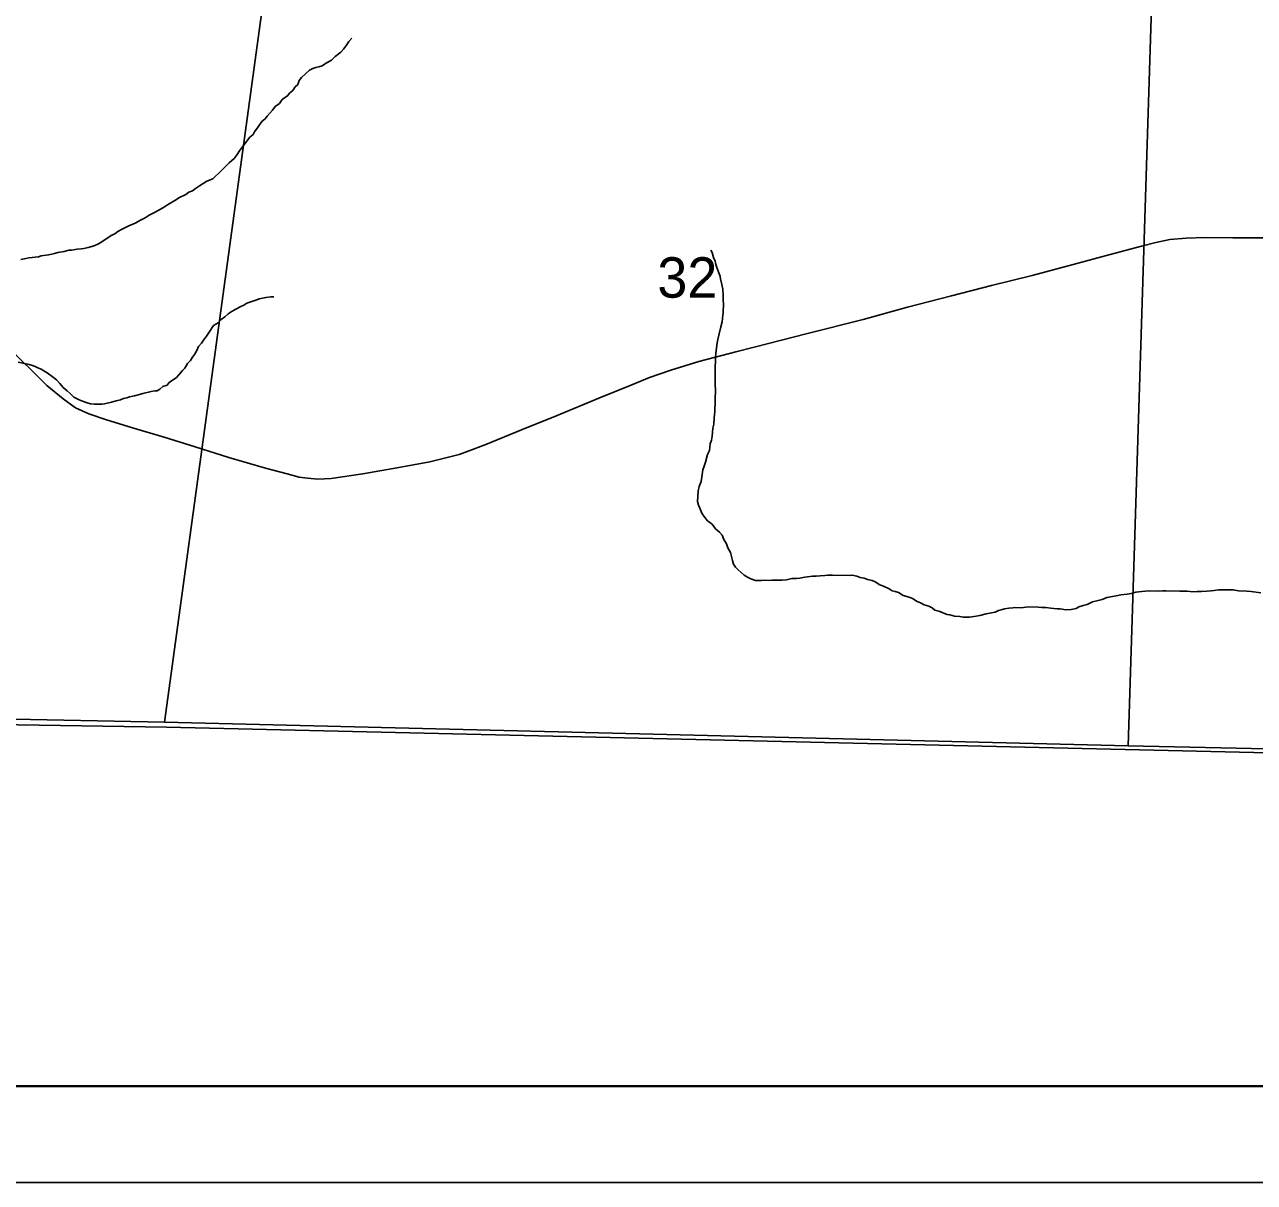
# Model space of a CAD drawing. Extents: x 0 to 34, y -2.3 to 22.
# Drawn here: x 3.123 to 4.399, y 14 to 15.2 of the extents above; entities that cross this region are included whole.
import ezdxf

# ---------------------------------------------------------------- set-up
doc = ezdxf.new("R2010")
doc.units = 0
for name, color, linetype in [('GM_X_Adjacent_County', 7, 'Continuous'), ('GM_X_County', 7, 'Continuous'), ('GM_X_Minor_River', 7, 'Continuous'), ('GM_X_Section', 7, 'Continuous'), ('GM_X_Section_Text', 7, 'Continuous'), ('GM_X_State_Route', 7, 'Continuous'), ('GM_X_Township', 7, 'Continuous'), ('SH_Data', 7, 'Continuous')]:
    doc.layers.add(name, color=color, linetype=linetype)

msp = doc.modelspace()

# ---------------------------------------------------------------- linework, layer by layer
at = {"layer": 'GM_X_Adjacent_County'}
for p, q in [((3.2706, 14.4719), (2.4571, 14.4851)), ((4.8179, 14.4357), (3.2706, 14.4719)), ((2.0792, 14.0994), (8.8792, 14.0994))]:
    msp.add_line(p, q, dxfattribs=at)
at = {"layer": 'GM_X_County'}
for p, q in [((2.4571, 14.4851), (3.2706, 14.4719)), ((3.2706, 14.4719), (4.8179, 14.4357))]:
    msp.add_line(p, q, dxfattribs=at)
at = {"layer": 'GM_X_Minor_River'}
for p, q in [((3.4541, 15.1747), (3.4572, 15.1788)), ((3.4572, 15.1788), (3.4596, 15.1825)), ((3.4596, 15.1825), (3.4628, 15.1862)), ((3.4416, 15.1633), (3.4455, 15.167)), ((3.4455, 15.167), (3.4513, 15.1717)), ((3.4513, 15.1717), (3.4541, 15.1747)), ((3.4107, 15.1452), (3.4189, 15.1529)), ((3.4189, 15.1529), (3.4223, 15.1547)), ((3.4223, 15.1547), (3.4254, 15.1558)), ((3.4254, 15.1558), (3.4285, 15.1565)), ((3.4285, 15.1565), (3.4319, 15.1575)), ((3.4319, 15.1575), (3.4354, 15.1597)), ((3.4354, 15.1597), (3.4416, 15.1633)), ((3.4066, 15.1381), (3.4083, 15.1422)), ((3.4083, 15.1422), (3.4107, 15.1452)), ((3.3964, 15.1266), (3.398, 15.1292)), ((3.398, 15.1292), (3.4015, 15.1318)), ((3.4015, 15.1318), (3.4039, 15.1355)), ((3.4039, 15.1355), (3.4066, 15.1381)), ((3.3804, 15.1115), (3.3832, 15.1153)), ((3.3832, 15.1153), (3.3878, 15.1185)), ((3.3878, 15.1185), (3.3906, 15.1226)), ((3.3906, 15.1226), (3.3964, 15.1266)), ((3.3694, 15.0997), (3.3729, 15.1026)), ((3.3729, 15.1026), (3.3749, 15.1052)), ((3.3749, 15.1052), (3.3804, 15.1115)), ((3.3603, 15.0863), (3.3619, 15.0889)), ((3.3619, 15.0889), (3.3655, 15.0941)), ((3.3655, 15.0941), (3.3694, 15.0997)), ((3.3461, 15.0692), (3.3513, 15.0763)), ((3.3513, 15.0763), (3.3568, 15.0834)), ((3.3568, 15.0834), (3.3603, 15.0863)), ((3.3406, 15.0614), (3.3437, 15.0655)), ((3.3437, 15.0655), (3.3461, 15.0692)), ((3.3273, 15.0485), (3.3355, 15.057)), ((3.3355, 15.057), (3.3406, 15.0614)), ((3.3048, 15.0329), (3.3125, 15.038)), ((3.3125, 15.038), (3.3187, 15.0404)), ((3.3187, 15.0404), (3.3273, 15.0485)), ((3.2905, 15.0242), (3.2936, 15.0264)), ((3.2936, 15.0264), (3.2974, 15.0278)), ((3.2974, 15.0278), (3.3005, 15.0303)), ((3.3005, 15.0303), (3.3048, 15.0329)), ((3.2673, 15.0104), (3.2715, 15.0133)), ((3.2715, 15.0133), (3.2808, 15.0188)), ((3.2808, 15.0188), (3.2835, 15.0206)), ((3.2835, 15.0206), (3.2905, 15.0242)), ((3.2437, 14.9975), (3.2483, 15)), ((3.2483, 15), (3.2526, 15.0025)), ((3.2526, 15.0025), (3.258, 15.0054)), ((3.258, 15.0054), (3.2673, 15.0104)), ((3.2202, 14.9856), (3.2237, 14.9878)), ((3.2237, 14.9878), (3.2314, 14.9917)), ((3.2314, 14.9917), (3.2379, 14.9942)), ((3.2379, 14.9942), (3.2437, 14.9975)), ((3.1993, 14.9726), (3.2024, 14.9744)), ((3.2024, 14.9744), (3.2132, 14.9817)), ((3.2132, 14.9817), (3.2171, 14.9834)), ((3.2171, 14.9834), (3.2202, 14.9856)), ((3.1404, 14.9603), (3.148, 14.9616)), ((3.148, 14.9616), (3.1515, 14.9622)), ((3.1515, 14.9622), (3.1545, 14.9629)), ((3.1545, 14.9629), (3.158, 14.9639)), ((3.158, 14.9639), (3.1645, 14.9649)), ((3.1645, 14.9649), (3.1691, 14.9663)), ((3.1691, 14.9663), (3.1721, 14.9665)), ((3.1721, 14.9665), (3.1778, 14.9675)), ((3.1778, 14.9675), (3.182, 14.9678)), ((3.182, 14.9678), (3.1847, 14.9681)), ((3.1847, 14.9681), (3.1893, 14.9691)), ((3.1893, 14.9691), (3.1931, 14.9701)), ((3.1931, 14.9701), (3.1962, 14.9711)), ((3.1962, 14.9711), (3.1993, 14.9726)), ((3.8365, 14.9638), (3.835, 14.9665)), ((3.8378, 14.9588), (3.8365, 14.9638)), ((3.1194, 14.9567), (3.1247, 14.9577)), ((3.1247, 14.9577), (3.1278, 14.9584)), ((3.1278, 14.9584), (3.1377, 14.9596)), ((3.1377, 14.9596), (3.1404, 14.9603)), ((3.8396, 14.955), (3.8378, 14.9588)), ((3.8403, 14.9515), (3.8396, 14.955)), ((3.8413, 14.9485), (3.8403, 14.9515)), ((3.8435, 14.9427), (3.8413, 14.9485)), ((3.8449, 14.9392), (3.8435, 14.9427)), ((3.8452, 14.9366), (3.8449, 14.9392)), ((3.8465, 14.9308), (3.8452, 14.9366)), ((3.8475, 14.9259), (3.8465, 14.9308)), ((3.8477, 14.9198), (3.8475, 14.9259)), ((3.3506, 14.9095), (3.3537, 14.9114)), ((3.3537, 14.9114), (3.3568, 14.9124)), ((3.3568, 14.9124), (3.3641, 14.9148)), ((3.3641, 14.9148), (3.3668, 14.9159)), ((3.3668, 14.9159), (3.3737, 14.9172)), ((3.3737, 14.9172), (3.3786, 14.9178)), ((3.3786, 14.9178), (3.3817, 14.9181)), ((3.848, 14.9167), (3.8477, 14.9198)), ((3.8479, 14.9137), (3.848, 14.9167)), ((3.8482, 14.911), (3.8479, 14.9137)), ((3.848, 14.9015), (3.8482, 14.911)), ((3.3309, 14.8972), (3.3344, 14.9005)), ((3.3344, 14.9005), (3.3387, 14.9031)), ((3.3387, 14.9031), (3.3433, 14.9056)), ((3.3433, 14.9056), (3.3476, 14.9081)), ((3.3476, 14.9081), (3.3506, 14.9095)), ((3.8469, 14.8921), (3.8475, 14.8989)), ((3.8475, 14.8989), (3.848, 14.9015)), ((3.3148, 14.8814), (3.3192, 14.8881)), ((3.3192, 14.8881), (3.3242, 14.891)), ((3.3242, 14.891), (3.3274, 14.8943)), ((3.3274, 14.8943), (3.3309, 14.8972)), ((3.8435, 14.8781), (3.8453, 14.8868)), ((3.8453, 14.8868), (3.8469, 14.8921)), ((3.3069, 14.8698), (3.3089, 14.8732)), ((3.3089, 14.8732), (3.3121, 14.8773)), ((3.3121, 14.8773), (3.3148, 14.8814)), ((3.8417, 14.8702), (3.8422, 14.8736)), ((3.8422, 14.8736), (3.8435, 14.8781)), ((3.2997, 14.8583), (3.3021, 14.8624)), ((3.3021, 14.8624), (3.3038, 14.8665)), ((3.3038, 14.8665), (3.3069, 14.8698)), ((3.8398, 14.8547), (3.8403, 14.8596)), ((3.8403, 14.8596), (3.8417, 14.8702)), ((3.1167, 14.8504), (3.128, 14.8478)), ((3.128, 14.8478), (3.1314, 14.8469)), ((3.1314, 14.8469), (3.1344, 14.8457)), ((3.2894, 14.8441), (3.2922, 14.849)), ((3.2922, 14.849), (3.2954, 14.8519)), ((3.2954, 14.8519), (3.2974, 14.8553)), ((3.2974, 14.8553), (3.2997, 14.8583)), ((3.8394, 14.8418), (3.8398, 14.8547)), ((3.1344, 14.8457), (3.137, 14.8445)), ((3.137, 14.8445), (3.1404, 14.8429)), ((3.1404, 14.8429), (3.1434, 14.8413)), ((3.1434, 14.8413), (3.1468, 14.8393)), ((3.1468, 14.8393), (3.1535, 14.8345)), ((3.1535, 14.8345), (3.1564, 14.8318)), ((3.2734, 14.829), (3.2808, 14.8345)), ((3.2808, 14.8345), (3.2832, 14.8371)), ((3.2832, 14.8371), (3.2871, 14.8415)), ((3.2871, 14.8415), (3.2894, 14.8441)), ((3.8397, 14.838), (3.8394, 14.8418)), ((3.8396, 14.8349), (3.8397, 14.838)), ((3.8397, 14.8262), (3.8396, 14.8349)), ((3.1564, 14.8318), (3.1598, 14.8282)), ((3.1598, 14.8282), (3.1634, 14.824)), ((3.1634, 14.824), (3.1675, 14.8204)), ((3.261, 14.8207), (3.2637, 14.8221)), ((3.2637, 14.8221), (3.2668, 14.825)), ((3.2668, 14.825), (3.2711, 14.8264)), ((3.2711, 14.8264), (3.2734, 14.829)), ((3.8393, 14.7992), (3.84, 14.8224)), ((3.84, 14.8224), (3.8397, 14.8262)), ((3.1675, 14.8204), (3.1705, 14.8177)), ((3.1705, 14.8177), (3.1745, 14.8141)), ((3.1745, 14.8141), (3.1798, 14.8113)), ((3.1798, 14.8113), (3.1835, 14.8097)), ((3.1835, 14.8097), (3.1881, 14.808)), ((3.1881, 14.808), (3.1918, 14.8071)), ((3.2063, 14.8071), (3.2135, 14.8088)), ((3.2135, 14.8088), (3.2185, 14.8102)), ((3.2185, 14.8102), (3.2227, 14.8112)), ((3.2227, 14.8112), (3.2258, 14.8126)), ((3.2258, 14.8126), (3.2293, 14.8133)), ((3.2293, 14.8133), (3.232, 14.8143)), ((3.232, 14.8143), (3.2373, 14.8153)), ((3.2373, 14.8153), (3.2427, 14.8167)), ((3.2427, 14.8167), (3.2461, 14.8177)), ((3.2461, 14.8177), (3.2545, 14.8197)), ((3.2545, 14.8197), (3.2584, 14.8204)), ((3.2584, 14.8204), (3.261, 14.8207)), ((3.1918, 14.8071), (3.1956, 14.8067)), ((3.1956, 14.8067), (3.1987, 14.8066)), ((3.1987, 14.8066), (3.2036, 14.8068)), ((3.2036, 14.8068), (3.2063, 14.8071)), ((3.8387, 14.7924), (3.8388, 14.7958)), ((3.8388, 14.7958), (3.8393, 14.7992)), ((3.8373, 14.7818), (3.8382, 14.786)), ((3.8382, 14.786), (3.8387, 14.7924)), ((3.8358, 14.7693), (3.8363, 14.7735)), ((3.8363, 14.7735), (3.8368, 14.7773)), ((3.8368, 14.7773), (3.8373, 14.7818)), ((3.8316, 14.7546), (3.8336, 14.7587)), ((3.8336, 14.7587), (3.8345, 14.7656)), ((3.8345, 14.7656), (3.8358, 14.7693)), ((3.8282, 14.7426), (3.8294, 14.7467)), ((3.8294, 14.7467), (3.8316, 14.7546)), ((3.8251, 14.7267), (3.8269, 14.7388)), ((3.8269, 14.7388), (3.8282, 14.7426)), ((3.8221, 14.7165), (3.823, 14.7214)), ((3.823, 14.7214), (3.8251, 14.7267)), ((3.8214, 14.7059), (3.8221, 14.7165)), ((3.8224, 14.7021), (3.8214, 14.7059)), ((3.8235, 14.699), (3.8224, 14.7021)), ((3.8256, 14.6936), (3.8235, 14.699)), ((3.8278, 14.6905), (3.8256, 14.6936)), ((3.8315, 14.6859), (3.8278, 14.6905)), ((3.8363, 14.6823), (3.8315, 14.6859)), ((3.84, 14.6776), (3.8363, 14.6823)), ((3.8441, 14.6741), (3.84, 14.6776)), ((3.847, 14.671), (3.8441, 14.6741)), ((3.8484, 14.6664), (3.847, 14.671)), ((3.8513, 14.6621), (3.8484, 14.6664)), ((3.8527, 14.6579), (3.8513, 14.6621)), ((3.8556, 14.6529), (3.8527, 14.6579)), ((3.8577, 14.6448), (3.8556, 14.6529)), ((3.8587, 14.641), (3.8577, 14.6448)), ((3.8605, 14.6379), (3.8587, 14.641)), ((3.8635, 14.6351), (3.8605, 14.6379)), ((3.8698, 14.6293), (3.8635, 14.6351)), ((3.9614, 14.6296), (3.9564, 14.6293)), ((3.9788, 14.629), (3.9614, 14.6296)), ((3.8731, 14.6273), (3.8698, 14.6293)), ((3.8765, 14.6256), (3.8731, 14.6273)), ((3.8814, 14.624), (3.8765, 14.6256)), ((3.8875, 14.6238), (3.8814, 14.624)), ((3.8905, 14.6241), (3.8875, 14.6238)), ((3.8951, 14.6239), (3.8905, 14.6241)), ((3.8985, 14.6242), (3.8951, 14.6239)), ((3.9038, 14.6244), (3.8985, 14.6242)), ((3.9091, 14.6243), (3.9038, 14.6244)), ((3.9137, 14.6245), (3.9091, 14.6243)), ((3.9191, 14.6259), (3.9137, 14.6245)), ((3.924, 14.6261), (3.9191, 14.6259)), ((3.9274, 14.6264), (3.924, 14.6261)), ((3.9324, 14.6274), (3.9274, 14.6264)), ((3.9355, 14.6277), (3.9324, 14.6274)), ((3.9404, 14.6283), (3.9355, 14.6277)), ((3.9442, 14.6285), (3.9404, 14.6283)), ((3.9484, 14.6288), (3.9442, 14.6285)), ((3.9534, 14.629), (3.9484, 14.6288)), ((3.9564, 14.6293), (3.9534, 14.629)), ((3.9815, 14.6293), (3.9788, 14.629)), ((3.9864, 14.6284), (3.9815, 14.6293)), ((3.9898, 14.6272), (3.9864, 14.6284)), ((3.994, 14.6263), (3.9898, 14.6272)), ((3.9974, 14.6251), (3.994, 14.6263)), ((4.0023, 14.6238), (3.9974, 14.6251)), ((4.0056, 14.6225), (4.0023, 14.6238)), ((4.0105, 14.6194), (4.0056, 14.6225)), ((4.0143, 14.6181), (4.0105, 14.6194)), ((4.0199, 14.6153), (4.0143, 14.6181)), ((4.0232, 14.6133), (4.0199, 14.6153)), ((4.0263, 14.6124), (4.0232, 14.6133)), ((4.0297, 14.6116), (4.0263, 14.6124)), ((4.0345, 14.6084), (4.0297, 14.6116)), ((4.0409, 14.6067), (4.0345, 14.6084)), ((4.0443, 14.6054), (4.0409, 14.6067)), ((4.0491, 14.6022), (4.0443, 14.6054)), ((4.2408, 14.6041), (4.2369, 14.6031)), ((4.2458, 14.6062), (4.2408, 14.6041)), ((4.2553, 14.6079), (4.2458, 14.6062)), ((4.2603, 14.6092), (4.2553, 14.6079)), ((4.2668, 14.6098), (4.2603, 14.6092)), ((4.271, 14.6104), (4.2668, 14.6098)), ((4.276, 14.6118), (4.271, 14.6104)), ((4.2821, 14.6124), (4.276, 14.6118)), ((4.2855, 14.6127), (4.2821, 14.6124)), ((4.2901, 14.6133), (4.2855, 14.6127)), ((4.2992, 14.613), (4.2901, 14.6133)), ((4.3038, 14.6133), (4.2992, 14.613)), ((4.3068, 14.6132), (4.3038, 14.6133)), ((4.3216, 14.6127), (4.3068, 14.6132)), ((4.3292, 14.6129), (4.3216, 14.6127)), ((4.3353, 14.6123), (4.3292, 14.6129)), ((4.3395, 14.6126), (4.3353, 14.6123)), ((4.344, 14.6124), (4.3395, 14.6126)), ((4.3494, 14.613), (4.344, 14.6124)), ((4.3539, 14.6133), (4.3494, 14.613)), ((4.357, 14.6136), (4.3539, 14.6133)), ((4.3616, 14.6142), (4.357, 14.6136)), ((4.3654, 14.6144), (4.3616, 14.6142)), ((4.3741, 14.6142), (4.3654, 14.6144)), ((4.3768, 14.6141), (4.3741, 14.6142)), ((4.3824, 14.6132), (4.3768, 14.6141)), ((4.3908, 14.6129), (4.3824, 14.6132)), ((4.3953, 14.6124), (4.3908, 14.6129)), ((4.4056, 14.611), (4.3953, 14.6124)), ((4.0525, 14.6006), (4.0491, 14.6022)), ((4.0563, 14.5986), (4.0525, 14.6006)), ((4.0612, 14.5973), (4.0563, 14.5986)), ((4.0645, 14.5957), (4.0612, 14.5973)), ((4.0675, 14.593), (4.0645, 14.5957)), ((4.0717, 14.5921), (4.0675, 14.593)), ((4.0743, 14.5912), (4.0717, 14.5921)), ((4.0773, 14.5896), (4.0743, 14.5912)), ((4.1333, 14.5929), (4.1298, 14.5911)), ((4.1363, 14.5936), (4.1333, 14.5929)), ((4.1398, 14.5946), (4.1363, 14.5936)), ((4.144, 14.5952), (4.1398, 14.5946)), ((4.1482, 14.5955), (4.144, 14.5952)), ((4.1512, 14.5958), (4.1482, 14.5955)), ((4.1561, 14.5956), (4.1512, 14.5958)), ((4.1592, 14.5959), (4.1561, 14.5956)), ((4.1642, 14.5965), (4.1592, 14.5959)), ((4.1744, 14.5962), (4.1642, 14.5965)), ((4.1782, 14.5961), (4.1744, 14.5962)), ((4.1824, 14.596), (4.1782, 14.5961)), ((4.1877, 14.5951), (4.1824, 14.596)), ((4.1907, 14.595), (4.1877, 14.5951)), ((4.1941, 14.5945), (4.1907, 14.595)), ((4.1972, 14.5944), (4.1941, 14.5945)), ((4.2032, 14.5935), (4.1972, 14.5944)), ((4.2089, 14.594), (4.2032, 14.5935)), ((4.2139, 14.595), (4.2089, 14.594)), ((4.2166, 14.5965), (4.2139, 14.595)), ((4.2212, 14.5979), (4.2166, 14.5965)), ((4.2254, 14.5989), (4.2212, 14.5979)), ((4.2308, 14.6018), (4.2254, 14.5989)), ((4.2369, 14.6031), (4.2308, 14.6018)), ((4.0803, 14.5888), (4.0773, 14.5896)), ((4.083, 14.5883), (4.0803, 14.5888)), ((4.0879, 14.587), (4.083, 14.5883)), ((4.0932, 14.5865), (4.0879, 14.587)), ((4.0966, 14.586), (4.0932, 14.5865)), ((4.1034, 14.5858), (4.0966, 14.586)), ((4.1103, 14.5871), (4.1034, 14.5858)), ((4.1141, 14.5878), (4.1103, 14.5871)), ((4.1206, 14.5895), (4.1141, 14.5878)), ((4.1263, 14.5904), (4.1206, 14.5895)), ((4.1298, 14.5911), (4.1263, 14.5904))]:
    msp.add_line(p, q, dxfattribs=at)
at = {"layer": 'GM_X_Section'}
for p, q in [((4.268, 14.4527), (4.2992, 15.4463)), ((4.2992, 15.4463), (4.268, 14.4527)), ((3.2685, 14.4772), (3.3991, 15.4295)), ((3.3991, 15.4295), (3.2685, 14.4772)), ((3.2685, 14.4772), (2.4645, 14.4918)), ((4.268, 14.4527), (3.2685, 14.4772)), ((5.2785, 14.4297), (4.268, 14.4527))]:
    msp.add_line(p, q, dxfattribs=at)
at = {"layer": 'GM_X_State_Route'}
for p, q in [((4.2817, 14.9704), (4.2967, 14.9743)), ((4.2967, 14.9743), (4.311, 14.9773)), ((4.311, 14.9773), (4.3282, 14.9788)), ((4.3282, 14.9788), (4.3479, 14.9794)), ((4.3479, 14.9794), (4.3764, 14.9792)), ((4.3764, 14.9792), (4.4183, 14.9792)), ((4.2107, 14.9515), (4.2494, 14.9617)), ((4.2494, 14.9617), (4.2817, 14.9704)), ((4.1682, 14.9402), (4.2107, 14.9515)), ((4.1262, 14.9296), (4.1682, 14.9402)), ((4.0846, 14.9189), (4.1262, 14.9296)), ((4.0391, 14.9072), (4.0846, 14.9189)), ((3.993, 14.8945), (4.0391, 14.9072)), ((3.9355, 14.8801), (3.993, 14.8945)), ((3.0965, 14.8745), (3.1308, 14.8417)), ((3.88, 14.8659), (3.9355, 14.8801)), ((3.8225, 14.851), (3.8609, 14.8608)), ((3.8609, 14.8608), (3.88, 14.8659)), ((3.7937, 14.8421), (3.8225, 14.851)), ((3.1308, 14.8417), (3.1464, 14.8261)), ((3.7532, 14.8269), (3.7716, 14.8343)), ((3.7716, 14.8343), (3.7937, 14.8421)), ((3.1464, 14.8261), (3.1633, 14.8122)), ((3.7188, 14.8128), (3.7532, 14.8269)), ((3.1633, 14.8122), (3.176, 14.8028)), ((3.6758, 14.7948), (3.7188, 14.8128)), ((3.176, 14.8028), (3.19, 14.7967)), ((3.19, 14.7967), (3.2082, 14.7903)), ((3.2082, 14.7903), (3.2387, 14.781)), ((3.6388, 14.78), (3.6758, 14.7948)), ((3.2387, 14.781), (3.268, 14.7724)), ((3.268, 14.7724), (3.3001, 14.7624)), ((3.6018, 14.7649), (3.6388, 14.78)), ((3.3001, 14.7624), (3.3353, 14.7515)), ((3.5742, 14.7546), (3.5835, 14.7581)), ((3.5835, 14.7581), (3.6018, 14.7649)), ((3.3353, 14.7515), (3.3733, 14.7405)), ((3.5114, 14.7409), (3.5435, 14.747)), ((3.5435, 14.747), (3.5617, 14.7513)), ((3.5617, 14.7513), (3.5742, 14.7546)), ((3.3733, 14.7405), (3.3957, 14.7345)), ((3.3957, 14.7345), (3.4082, 14.7311)), ((3.4412, 14.7298), (3.474, 14.7346)), ((3.474, 14.7346), (3.5114, 14.7409)), ((3.4082, 14.7311), (3.4168, 14.7299)), ((3.4168, 14.7299), (3.4275, 14.729)), ((3.4275, 14.729), (3.4412, 14.7298))]:
    msp.add_line(p, q, dxfattribs=at)
at = {"layer": 'GM_X_Township'}
for p, q in [((3.2706, 14.4719), (2.4571, 14.4851)), ((4.8179, 14.4357), (3.2706, 14.4719))]:
    msp.add_line(p, q, dxfattribs=at)
at = {"layer": 'SH_Data'}
for p, q in [((2.1, 14.1), (8.9, 14.1)), ((2, 14), (9, 14))]:
    msp.add_line(p, q, dxfattribs=at)

# ---------------------------------------------------------------- texts
at = {"layer": 'GM_X_Section_Text'}
msp.add_text('32', height=0.04186, rotation=0, dxfattribs=at).set_placement((3.7796, 14.9171))

doc.saveas('drawing.dxf')
